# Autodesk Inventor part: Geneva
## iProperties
Shininess: 64.0
Length Units: 11269
Angle Units: 11279
Time Units: 11290
Mass Units: 11283
Length Display Precision: 3
Angle Display Precision: 2
Compacted: True
Part Number: Geneva
Document SubType Name: Modeling
Created: 2003-08
Designer: 40664
Manufacturer: Standard
Standards Organization: Custom
Density: 0.0
Volumn: 0.0
Area: 0.0
PropertySet Name: Model Information
Control State: 0
Master: False
Checked Out: False
Author: 40664
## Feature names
1. Revolution1
2. Shell1
3. Extrusion1
4. Hole1
5. Revolution2
6. Fillet2
7. Circular Pattern2
8. Extrusion2
9. FaceDraft1
10. FaceDraft2
11. Fillet3
12. Circular Pattern1
13. Fillet4
